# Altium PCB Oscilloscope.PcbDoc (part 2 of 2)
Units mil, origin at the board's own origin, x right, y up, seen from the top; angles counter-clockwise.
Board outline 3937.5 x 3937.5 mil, 4 copper layers (Layer 1, Layer 2, Layer 3, Layer 4), stack 68.734 mil thick; 84 components, 72 nets, 418 pads, 204 vias.
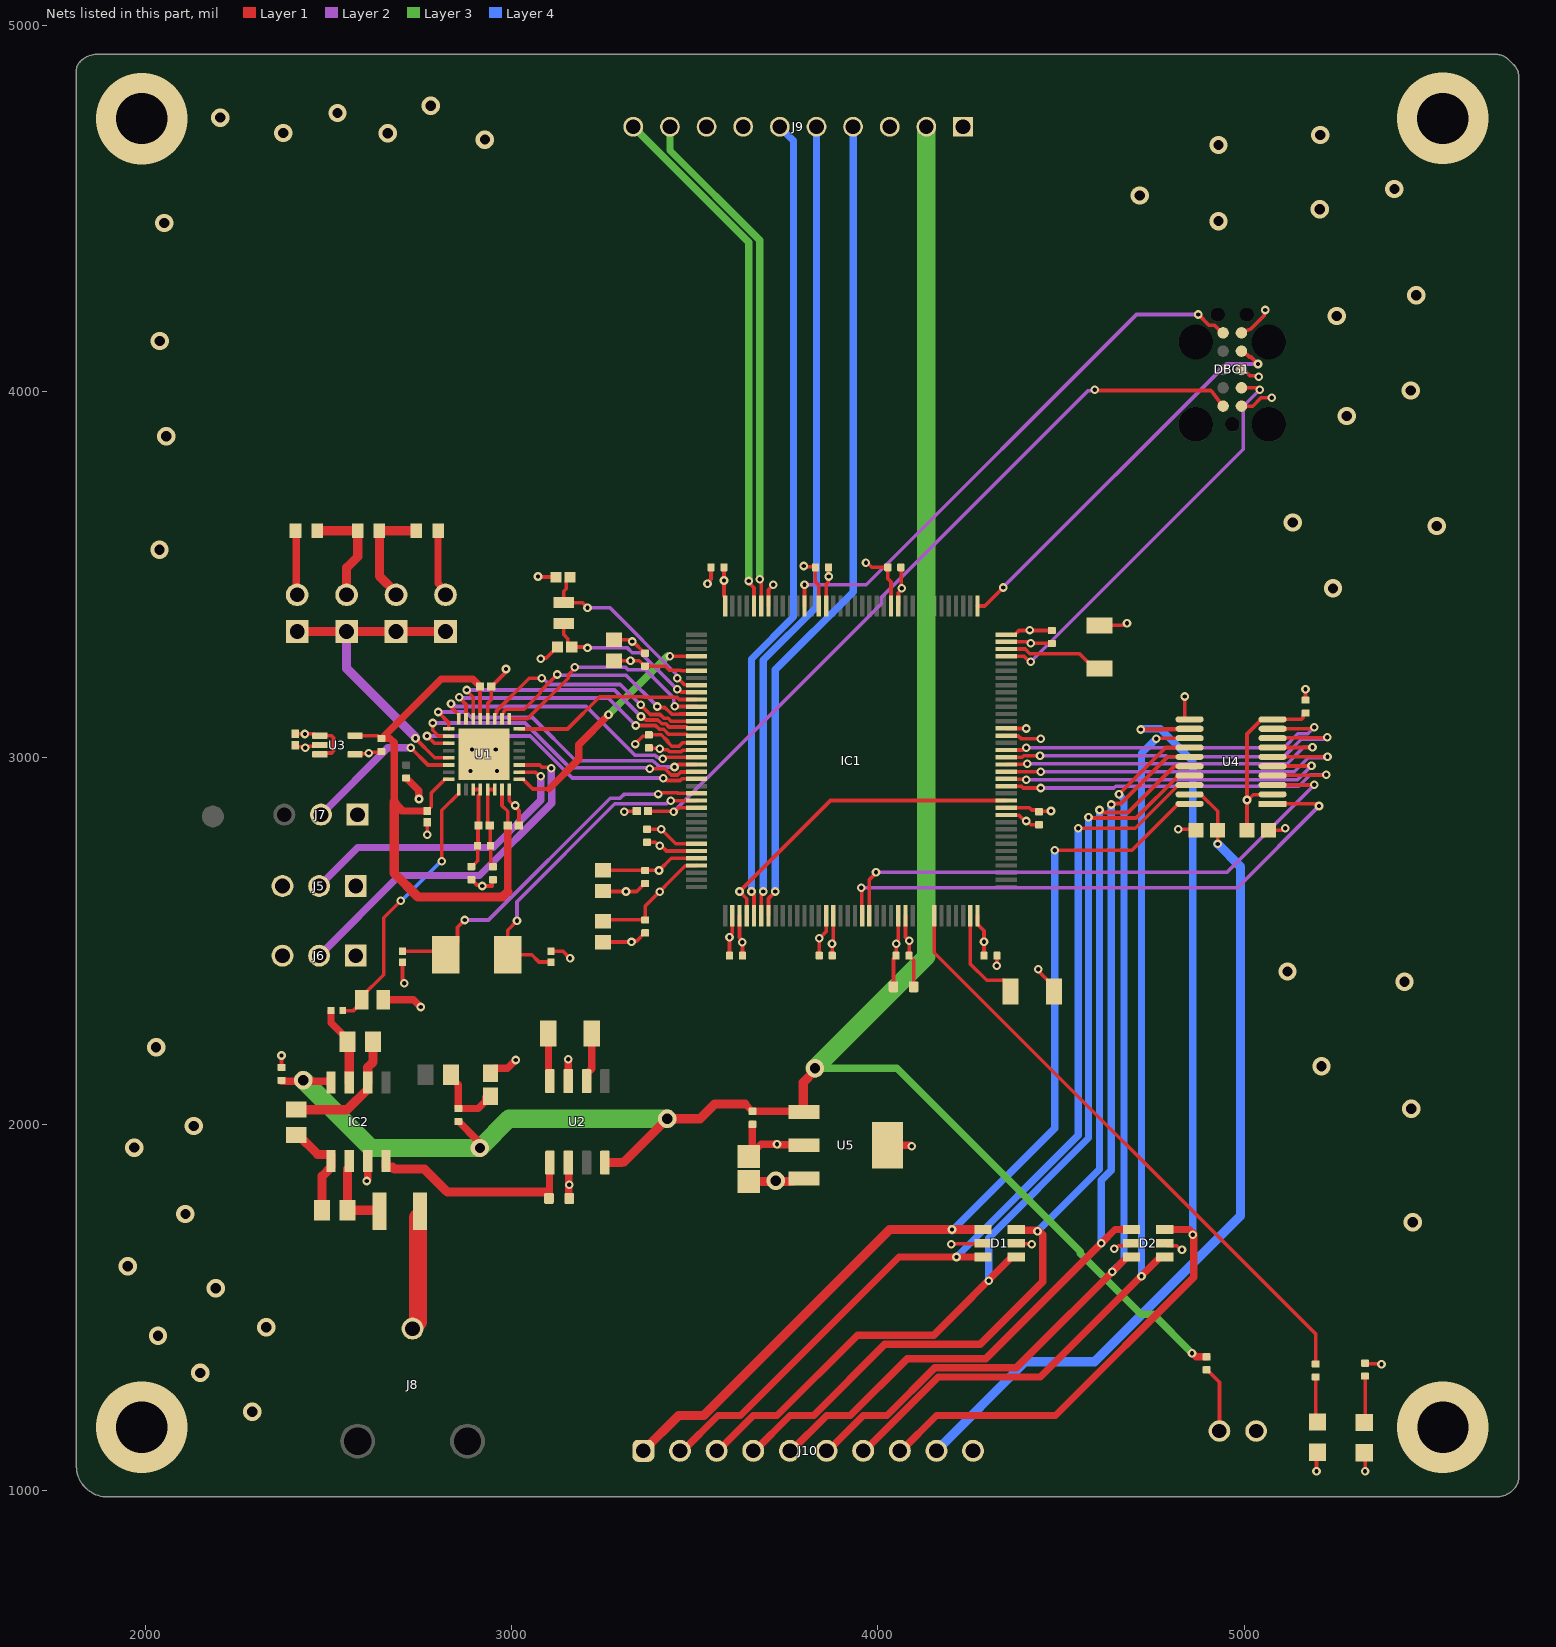
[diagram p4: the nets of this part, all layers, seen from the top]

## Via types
v1: diameter 23.62, hole 11.81, Layer 1 to Layer 4, tented top, 157 vias
v2: diameter 50, hole 28, Layer 1 to Layer 4, 43 vias
v3: diameter 250, hole 140, Layer 1 to Layer 4, 4 vias

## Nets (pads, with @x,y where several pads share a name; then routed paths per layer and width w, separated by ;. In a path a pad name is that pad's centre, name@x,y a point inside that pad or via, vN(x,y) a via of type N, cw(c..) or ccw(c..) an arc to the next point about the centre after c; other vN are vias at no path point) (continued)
3V3: C12.2 C19.2 C20.2 C21.2 C22.2 C23.2 C25.2 C26.2 C27.2 C28.2 C29.2 C30.2 C31.2 C32.2 C33.2 C34.2 C35.2 C36.2 C37.2 C38.2 C40.2 DBG1.1 IC1.6 IC1.17 IC1.30 IC1.32 IC1.33 IC1.39 IC1.52 IC1.62 IC1.72 IC1.84 IC1.95 IC1.108 IC1.121 IC1.131 IC1.144 J1.2 J5.1 J6.1 J7.1 R1.2 R4.2 R13.1 U3.1 U3.3 U4.2 U4.10 U5.3 | length 3599.8
  Layer 1 w10: C12.2@2410,3065.35 2460.2,3065.35 2464.96,3060.59 U3.1@2476.77,3060.59 2508.55,3060.59 2514.41,3054.73 2514.41,3019.13 2508.55,3013.27 2480.63,3013.27 U3.3@2476.77,3009.41 ; C20.2@3250,2553.54 3254.17,2557.72 C19.2@3365,2557.72 3365,2595.7 3474.7,2705.39 3504.09,2705.39 IC1.33@3505,2706.3 ; C38.2@3250,2693.54 3250.83,2692.72 C37.2@3365,2692.72 3402.72,2692.72 3435.98,2725.98 IC1.32@3505,2725.98 ; C22.2@3280,3265 v1(3324.77,3265) 3349.02,3265 3364.02,3250 3420.25,3250 3430.94,3239.31 3461.53,3239.31 3463.05,3237.8 IC1.6@3505,3237.8 ; C35.2@3370,2805 3409.03,2805 3448.67,2765.35 IC1.30@3505,2765.35 ; C36.2@3375,3027.28 3376.14,3026.14 3403.86,3026.14 3407.61,3022.39 3425.8,3022.39 3431.62,3016.57 3463.38,3016.57 3467.16,3020.35 3504.09,3020.35 IC1.17@3505,3021.26 ; C32.2@3580,3520 v1(3580,3484.13) 3580,3440.89 3583.27,3437.62 IC1.144@3583.27,3414.49 ; IC1.39@3622.64,2568.98 3622.64,2509.73 3630.43,2501.94 C27.2@3630.43,2460 ; v1(3797.5,3523.69) 3799.34,3521.84 3827.72,3521.84 C33.2@3829.57,3520 3829.57,3480.7 3839.17,3471.09 IC1.131@3839.17,3414.49 ; C28.2@3875.43,2460 3875.22,2460.22 3875.22,2492.28 v1(3875,2492.5) 3875,2496.19 3878.54,2499.73 IC1.52@3878.54,2568.98 ; v1(3967.5,3532.5) 3971.19,3532.5 3983.69,3520 C34.2@4027.28,3520 4027.39,3519.89 4027.39,3492.61 4027.5,3492.5 4027.5,3488.81 4036.02,3480.29 IC1.121@4036.02,3414.49 ; IC1.62@4075.39,2568.98 4075.39,2510.86 v1(4085.43,2500.82) C26.2@4085.43,2460 4085.43,2459.02 4097.72,2446.73 C25.2@4097.72,2375 ; IC1.72@4272.24,2568.98 4272.24,2545.85 4290,2528.09 v1(4290,2497.73) C29.2@4290,2460 ; IC1.84@4350.51,2863.78 4413.73,2863.78 4419.95,2857.56 4435.16,2857.56 C30.2@4440,2852.72 4441.14,2853.86 4471.36,2853.86 v1(4472.5,2855) ; IC1.95@4350.51,3080.32 4350.67,3080.16 4404.84,3080.16 v1(4405,3080) ; IC1.108@4350.51,3336.22 4373.64,3336.22 4385.14,3347.72 C31.2@4475,3347.72 ; DBG1.1@4992.5,3960 5023.57,3960 5046.07,3982.5 v1(5075,3982.5) ; C23.2@5007.5,2802.5 v1(5007.5,2885) ; U4.2@5077.5,2900.14 5076.24,2898.88 5025.07,2898.88 5011.19,2885 v1(5007.5,2885) ; R4.2@5167.5,3122.07 5166.52,3122.07 5161.67,3117.22 5161.67,3110.72 5155.82,3104.86 5047.02,3104.86 5007.5,3065.34 v1(5007.5,2885) ; R13.1@5330,1347.72 5331.36,1346.36 5373.64,1346.36 v1(5375,1345)
  Layer 1 w20: R1.2@2799.53,3620 2799.53,3476.79 2820,3456.31 J1.2@2820,3445
  Layer 1 w25: C40.2@3647.5,1843.48 3766.24,1843.48 3774.7,1851.95 U5.3@3798.33,1851.95
  other v1: 3630,2496.19 3404.8,2634.8 3402.51,2692.51 3408.82,2804.8 3405,3025 2436.21,3065.15 4415,3348.69
  other v2: 3721.31,1845.34
3V3_ADC: C6.2 C8.2 C9.2 C13.1 U1.7 U1.21 U1.32 U3.5 | length 1746.9
  Layer 1 w10: U3.5@2573.23,3060.59 2636.14,3060.59 2644.02,3052.72 C13.1@2645,3052.72 ; C8.2@2770,2855.79 2780.9,2866.68 2780.9,2904.3 2817.7,2941.1 U1.32@2828.45,2941.1 ; C9.2@2914.29,3195 2914.29,3118.17 2915.16,3117.3 U1.21@2915.16,3106.55 ; U1.7@2974.21,2913.45 2974.21,2869.38 2989.65,2853.95 C6.2@2989.65,2815
  Layer 1 w20: 2700,2855 C8.2@2770,2855 ; 2700,2860 2680,2880 2680,3041 2668.28,3052.72 C13.1@2645,3052.72 2645.67,3052.72 2807.95,3215 2894.29,3215 2912.87,3196.42 2912.87,3195.63 2913.5,3195 C9.2@2914.29,3195 ; 2989.65,2634.65 C6.2@2989.65,2815
  Layer 1 w25: 2680,2880 2680,2685 2745,2620 2975,2620 2989.65,2634.65
5V_BUS: C17.1 C39.2 IC2.8 J9.02 R12.1 R26.1 U2.8 U5.1 | length 6149.2
  Layer 1 w20: C17.1@2372.5,2117.28 2504.7,2117.28 2507.5,2114.49 IC2.8@2507.5,2113.54 ; R26.1@2855,2007.28 2855.67,2007.28 v2@2908.33,1954.62 ; 3637.72,2055 3656.67,2036.04 3656.67,2035.37 3656.83,2035.22 C39.2@3657.5,2035.22 ; C39.2@3657.66,2035.06 U5.1@3796.32,2035.06 ; v1(4857.5,1375) 4858.48,1375 4868.32,1365.16 4897.34,1365.16 R12.1@4897.5,1365
  Layer 1 w25: U2.8@3255,1895.06 3300,1895.06 ; 3307.56,1897.56 v2(3425,2015) 3514.74,2015 3554.74,2055 3637.72,2055 ; U5.1@3796.32,2035.06 3796.32,2113.86 3828.27,2145.81 v2(3828.27,2152.58)
  Layer 3 w20: v2(3828.27,2152.58) 4052.42,2152.58 4552.5,1652.5 4552.5,1646.87 4718.38,1480.99 4751.51,1480.99 v1(4857.5,1375)
  Layer 3 w50: v2(2431.73,2120.22) 2616.73,1935.22 v2(2913.85,1935.22) 2993.64,2015 v2(3425,2015) ; v2(3828.27,2152.58) 3828.19,2152.5 3827.5,2152.5 4132.5,2457.5 J9.02@4132.5,4722.5
-5V: C16.2 IC2.4 U2.5 | length 580.3
  Layer 1 w20: C16.2@3102.44,1797.5 3103.72,1798.78 3103.72,1893.78 U2.5@3105,1895.06
  Layer 1 w25: IC2.4@2657.5,1900 2657.5,1882.78 2657.8,1882.48 2675.02,1882.48 2680,1877.5 2762.5,1877.5 2822.44,1817.56 ; 2825,1815.06 3097.5,1815.06
ADC_CLK: IC1.4 U1.9 | length 667.9
  Layer 1 w10: U1.9@3021.55,2941.1 3032.3,2941.1 3058.4,2915 3102.44,2915 ; v1(3432.5,3277.5) 3432.67,3277.33 3504.83,3277.33 IC1.4@3505,3277.17
  Layer 1 w20: 3102.44,2915 3183.37,2995.94 3183.37,3035.87 v1(3265,3117.5)
  Layer 3 w20: v1(3265,3117.5) 3425,3277.5 v1(3432.5,3277.5)
ANA_IN: J8.1 R5.1 | length 309.3
  Layer 1 w50: J8.1@2730,1442 2730,1444.71 2745.12,1459.82 R5.1@2745.12,1745
ANA_IN_FILT: C48.1 R9.2 U1.1 | length 744.1
  Layer 1 w10: R9.2@2539.17,2310 2568.82,2310 2590.94,2332.13 C48.1@2590.94,2340 2590.94,2347.87 2651.07,2408 2651.07,2563.57 v1(2697.5,2610) ; v1(2810,2717.5) 2810,2856.6 U1.1@2856.01,2902.61
  Layer 4 w10: v1(2697.5,2610) 2700,2610 2807.5,2717.5 v1(2810,2717.5)
ANA_IN_HIGH: IC2.7 R8.2 R9.1 | length 217.2
  Layer 1 w20: R9.1@2507.5,2310 2507.5,2276.46 2553.01,2230.95 R8.2@2553.01,2225
  Layer 1 w25: R8.2@2553.01,2225 2557.2,2220.8 2557.2,2113.84 IC2.7@2557.5,2113.54
D0: IC1.10 U1.16 | length 523.1
  Layer 1 w10: U1.16@3021.55,3078.9 3153.01,3078.9 3240.92,3166.81 3361.53,3166.81 3362.66,3165.69 3451.95,3165.69 3458.59,3159.06 IC1.10@3505,3159.06
D1: IC1.11 U1.17 | length 632.3
  Layer 1 w10: U1.17@2993.9,3106.55 3044.05,3106.55 3155.01,3217.51 3155.01,3226.39 3172.5,3243.88 v1(3172.5,3246.81) ; v1(3445.7,3141.1) 3446.56,3140.23 3504.14,3140.23 IC1.11@3505,3139.37
  Layer 2 w10: v1(3172.5,3246.81) 3312.11,3246.81 3318.92,3240 3366.69,3240 3443.09,3163.59 3443.09,3143.7 v1(3445.7,3141.1)
D2: IC1.12 U1.18 | length 637.7
  Layer 1 w10: U1.18@2974.21,3106.55 2974.21,3117.3 2978.99,3122.08 2978.99,3126.54 2984.85,3132.39 3034.89,3132.39 3078.64,3176.14 3078.64,3181.14 v1(3125,3227.5) ; v1(3398.32,3140.17) 3400.92,3137.56 3418.39,3137.56 3433.23,3122.72 3433.96,3122.72 3437.39,3119.29 3459.27,3119.29 3459.67,3119.69 IC1.12@3505,3119.69
  Layer 2 w10: v1(3125,3227.5) 3127.5,3225 3313.49,3225 v1(3398.32,3140.17)
D3: IC1.13 U1.19 | length 644
  Layer 1 w10: U1.19@2954.62,3117.39 2959.21,3121.98 2959.21,3127.97 3048.74,3217.5 v1(3082.5,3217.5) ; v1(3352.5,3145) 3379.14,3118.36 3405.72,3118.36 3416.36,3107.72 3427.74,3107.72 3435.46,3100 IC1.13@3505,3100
  Layer 2 w10: v1(3082.5,3217.5) 3085.89,3217.5 3103.16,3200.24 3297.26,3200.24 v1(3352.5,3145)
D4: IC1.14 U1.22 | length 756.8
  Layer 1 w10: v1(2877.74,3185.24) 2877.74,3182.79 2895.47,3165.06 U1.22@2895.47,3106.55 ; v1(3353.78,3112.88) 3357.46,3112.88 3366.98,3103.36 3399.5,3103.36 3410.15,3092.72 3421.53,3092.72 3430.15,3084.09 3478.09,3084.09 3481.87,3080.32 IC1.14@3505,3080.32
  Layer 2 w10: v1(2877.74,3185.24) 3281.42,3185.24 v1(3353.78,3112.88)
D5: IC1.15 U1.23 | length 756.8
  Layer 1 w10: v1(2857.5,3165) 2857.5,3163.66 2875.79,3145.37 U1.23@2875.79,3106.55 ; v1(3339.01,3088.36) 3393.29,3088.36 3403.93,3077.72 3415.32,3077.72 3428.62,3064.41 3478.09,3064.41 3481.87,3060.63 IC1.15@3505,3060.63
  Layer 2 w10: v1(2857.5,3165) 2859.07,3163.43 3263.94,3163.43 v1(3339.01,3088.36)
D6: IC1.18 U1.24 | length 783.6
  Layer 1 w10: v1(2834.91,3147.43) 2837.51,3144.82 2837.51,3135.89 2856.1,3117.3 U1.24@2856.1,3106.55 ; v1(3412.53,2997.39) 3416.22,2997.39 3420.41,3001.57 IC1.18@3505,3001.57
  Layer 2 w10: v1(2834.91,3147.43) 2838.59,3147.43 2846.02,3140 3204.15,3140 3336.98,3007.17 3391.98,3007.17 3395.97,3003.19 3397.1,3003.19 3400.29,2999.99 3409.92,2999.99 v1(3412.53,2997.39)
D7: IC1.19 U1.25 | length 827.9
  Layer 1 w10: v1(2800,3125) 2828.45,3096.55 U1.25@2828.45,3078.9 ; v1(3445,2975) 3448.69,2975 3455.58,2981.89 IC1.19@3505,2981.89
  Layer 2 w10: v1(2800,3125) 2875.47,3125 2890.47,3110 3057.5,3110 3175.33,2992.17 3385.77,2992.17 3389.75,2988.19 3390.88,2988.19 3404.07,2975 v1(3445,2975)
D8: IC1.20 U1.26 | length 852.7
  Layer 1 w10: v1(2785,3095) 2785,3075 2800.79,3059.21 U1.26@2828.45,3059.21 ; v1(3377.65,2970.04) 3377.97,2970.36 3418.79,2970.36 3435.97,2953.19 3454.03,2953.19 3462.14,2961.3 3504.09,2961.3 IC1.20@3505,2962.2
  Layer 2 w10: v1(2785,3095) 3037.06,3095 3159.56,2972.5 3375.19,2972.5 v1(3377.65,2970.04)
D9: IC1.21 U1.27 | length 854.7
  Layer 1 w10: v1(2769.58,3059.58) 2789.63,3039.53 U1.27@2828.45,3039.53 ; v1(3414.15,2944.15) 3417.84,2944.15 3423.81,2938.19 3460.25,2938.19 3464.58,2942.52 IC1.21@3505,2942.52
  Layer 2 w10: v1(2769.58,3059.58) 3051.27,3059.58 3165.85,2945 3413.31,2945 v1(3414.15,2944.15)
Debug: IC1.66 R14.1 | length 1654.7
  Layer 1 w10: IC1.66@4154.13,2568.98 4154.13,2468.04 5195,1427.18 R14.1@5195,1345.43
DIN_1: D1.1 J10.1 U4.20 | length 2756.1
  Layer 1 w10: v1(4482.5,2747.5) 4693.83,2747.5 4818.74,2872.4 4848.95,2872.4 U4.20@4851.09,2874.55
  Layer 1 w25: J10.1@3360,1108.51 3456.49,1205 3525,1205 4032.4,1712.4 D1.1@4287.22,1712.4
  Layer 4 w20: v1(4202.39,1712.39) 4202.39,1709.2 4482.5,1989.31 v1(4482.5,2747.5)
DIN_2: D1.3 J10.2 U4.18 | length 2706.8
  Layer 1 w10: v1(4547.5,2807.5) 4702.39,2807.5 4818.6,2923.72 4849.08,2923.72 U4.18@4851.09,2925.73
  Layer 1 w20: J10.2@3460,1108.51 3467.4,1108.51 3563.89,1205 3625,1205 4057.6,1637.6 D1.3@4287.22,1637.6
  Layer 4 w20: v1(4214.89,1637.39) 4547.5,1970 v1(4547.5,2807.5)
DIN_3: D1.4 J10.3 U4.17 | length 2737.1
  Layer 1 w10: v1@4576.81,2835.69 4704.99,2835.69 4820.62,2951.32 U4.17@4851.09,2951.32
  Layer 1 w20: J10.3@3560,1108.51 3563.86,1108.51 3660.36,1205 3725,1205 3944.32,1424.32 4152.68,1424.32 4365.96,1637.6 D1.4@4377.78,1637.6
  Layer 4 w20: v1(4302.39,1572.39) 4302.39,1689.54 4575,1962.14 v1(4575,2837.5)
DIN_4: D1.6 J10.4 U4.16 | length 2705.9
  Layer 1 w10: v1@4605,2850.69 4683.19,2850.69 4808.68,2976.18 4850.36,2976.18 U4.16@4851.09,2976.91
  Layer 1 w20: J10.4@3660,1108.51 3663.86,1108.51 3760.36,1205 3825,1205 4019.32,1399.32 4279.32,1399.32 4450,1570 4450,1698.87 4438.28,1710.59 4379.59,1710.59 D1.6@4377.78,1712.4
  Layer 4 w20: v1(4435.68,1707.98) 4605,1877.31 v1(4605,2857.5)
DIN_5: D2.1 J10.5 U4.15 | length 2659.1
  Layer 1 w10: v1(4637.5,2872.5) 4640.11,2875.11 4663.45,2875.11 4790.85,3002.5 U4.15@4851.09,3002.5
  Layer 1 w20: J10.5@3760,1108.51 3763.86,1108.51 3860.36,1205 3925,1205 4080,1360 4295,1360 v1(4609.89,1674.89) 4647.4,1712.4 D2.1@4692.5,1712.4
  Layer 4 w20: v1(4609.89,1674.89) 4609.89,1846.84 4637.5,1874.45 v1(4637.5,2872.5)
DIN_6: D2.3 J10.6 U4.14 | length 2619.4
  Layer 1 w10: v1(4658.27,2900.77) 4785.59,3028.09 U4.14@4851.09,3028.09
  Layer 1 w20: J10.6@3860,1108.51 3863.86,1108.51 3960.36,1205 4025,1205 4155,1335 4378.09,1335 4680.69,1637.6 D2.3@4692.5,1637.6
  Layer 4 w20: v1(4639.89,1597.39) 4671.81,1629.31 4671.81,2886.26 4658.27,2899.79 v1(4658.27,2900.77)
DIN_7: D2.4 J10.7 U4.13 | length 2618
  Layer 1 w10: v1(4760,3052.5) 4760.59,3053.09 4850.5,3053.09 U4.13@4851.09,3053.68
  Layer 1 w20: J10.7@3960,1108.51 3963.86,1108.51 4165.36,1310 4443.64,1310 4719.21,1585.57 4771.24,1637.6 D2.4@4783.05,1637.6
  Layer 4 w20: v1(4719.89,1584.89) 4719.89,3012.39 v1(4760,3052.5)
DIN_8: D2.6 J10.8 U4.12 | length 2808
  Layer 1 w12: v1(4717.5,3077.5) 4718.4,3078.4 4850.22,3078.4 U4.12@4851.09,3079.27
  Layer 1 w20: J10.8@4060,1108.51 4063.86,1108.51 4160.36,1205 4485,1205 4862.5,1582.5 4862.5,1700.69 4850.78,1712.4 D2.6@4783.05,1712.4
  Layer 4 w20: v1(4717.5,3077.5) 4718.48,3077.5 4720.29,3079.31 4771.11,3079.31 4859.89,2990.52 v1(4859.89,1698.08)
GND: C1.1 C4.2 C5.2 C6.1 C7.1 C8.1 C9.1 C12.1 C13.2 C16.1 C17.2 C19.1 C20.1 C21.1 C22.1 C23.1 C24.1 C25.1 C26.1 C27.1 C28.1 C29.1 C30.1 C31.1 C32.1 C33.1 C34.1 C35.1 C36.1 C37.1 C38.1 C39.1 C40.1 C42.1 C43.1 C44.1 C45.1 C46.2 C47.2 C48.2 D1.2 D1.5 D2.2 D2.5 D3.2 D4.1 D5.1 DBG1.3 DBG1.5 IC1.16 IC1.31 IC1.38 IC1.51 IC1.61 IC1.83 IC1.94 IC1.107 IC1.120 IC1.130 IC1.138 IC2.3 J4.2 J5.3 J6.3 J9.01 J9.03 J9.07 J9.08 J10.10 R3.1 R4.1 R27.2 U1.8 U1.20 U1.33 U2.3 U2.6 U3.2 U3.4 U4.11 U5.2 U5.4 | length 4472.8
  Layer 1 w10: C17.2@2372.5,2155 v1(2372.5,2187.5) ; C12.1@2410,3034.65 2414.54,3030.11 2434.89,3030.11 v1(2437.5,3027.5) 2441.19,3027.5 2444.83,3031.14 2472.91,3031.14 U3.2@2476.77,3035 ; U3.4@2573.23,3009.41 2575,3011.18 2608.27,3011.18 v1(2610.04,3012.95) ; v1@2610.04,3009.41 2615.75,3015.12 2642.84,3015.12 C13.2@2645,3017.28 ; C46.2@2702.5,2442.6 2702.5,2393.69 2707.5,2388.69 v1(2707.5,2385) ; v1(2770,2790) C8.1@2770,2824.29 ; C4.2@2890.35,2667.28 2891.34,2667.28 2906.02,2652.61 2917.39,2652.61 v1(2920,2650) 2947.28,2650 2947.28,2664.57 C5.2@2950,2667.28 ; U1.20@2934.84,3106.55 2934.84,3148.26 2945,3158.41 C9.1@2945,3195 2945.79,3195 2985,3234.21 v1(2985,3242.5) ; U1.8@2993.9,2913.45 2993.9,2882.61 3006.5,2870 v1(3010,2870) 3010,2866.31 3020.35,2855.96 C6.1@3020.35,2815 ; v1(3072.5,3495) 3073.75,3493.75 3120.17,3493.75 C44.1@3121.42,3492.5 ; v1(3080,3270) 3082.61,3272.61 3095.03,3272.61 3124.92,3302.5 C45.1@3125.71,3302.5 ; C47.2@3107.5,2472.4 3140.1,2472.4 v1(3160,2452.5) ; C20.1@3250,2496.46 3251.04,2497.5 v1(3327.5,2497.5) 3330.11,2500.11 3341.84,2500.11 3364.02,2522.28 C19.1@3365,2522.28 ; C38.1@3250,2636.46 3251.46,2635 3341.73,2635 3364.02,2657.28 C37.1@3365,2657.28 ; C22.1@3280,3322.09 3321.73,3322.09 3326.31,3317.5 3331.95,3317.5 3364.02,3285.43 C21.1@3365,3285.43 ; v1(3307.5,2852.5) 3308.75,2853.75 3340.9,2853.75 C1.1@3342.15,2855 ; v1(3337.5,3037.5) 3358.64,3058.64 3369.94,3058.64 3374.02,3062.72 3409.1,3062.72 3425.69,3046.13 3425.69,3043.72 3437.84,3031.57 3457.16,3031.57 3466.53,3040.94 IC1.16@3505,3040.94 ; C35.1@3370,2769.57 3392.85,2769.57 3402.42,2760 3408.69,2760 3423.02,2745.67 IC1.31@3505,2745.67 ; v1(3535,3475) 3535,3478.69 3544.57,3488.25 C32.1@3544.57,3520 ; C27.1@3595,2460 3595,2513.69 3602.95,2521.64 IC1.38@3602.95,2568.98 ; IC1.138@3701.38,3414.49 3701.38,3458.52 3715,3472.15 v1(3715,3472.5) ; C28.1@3840,2460 v1(3840,2507.5) 3841.42,2507.5 3858.86,2524.94 IC1.51@3858.86,2568.98 ; IC1.130@3858.86,3414.49 3858.86,3472.82 3865,3478.97 C33.1@3865,3520 ; C25.1@4042.6,2375 4042.6,2451.61 4050,2459.02 4050,2496.19 4055.71,2501.89 IC1.61@4055.71,2568.98 ; IC1.120@4055.71,3414.49 4056.61,3415.39 4056.61,3450.43 4065,3458.81 v1(4065,3462.5) 4063.86,3463.64 4063.86,3518.86 C34.1@4062.72,3520 ; v1(4200,1672.5) 4201.25,1673.75 4285.97,1673.75 D1.2@4287.22,1675 ; v1(4325,2432.5) 4325.22,2432.72 4325.22,2459.78 C29.1@4325.43,2460 ; IC1.83@4350.51,2844.09 4351.42,2843.19 4385.62,2843.19 4401.31,2827.5 4406.93,2827.5 4417.15,2817.28 C30.1@4440,2817.28 ; IC1.94@4350.51,3060.63 4351.42,3059.72 4383.6,3059.72 4390.83,3052.5 v1(4445,3052.5) ; IC1.107@4350.51,3316.54 4409.78,3316.54 4413.81,3312.5 v1(4417.5,3312.5) 4417.61,3312.39 4474.89,3312.39 C31.1@4475,3312.28 ; D1.5@4377.78,1675 4379.03,1673.75 4418.75,1673.75 v1(4420,1672.5) ; v1(4437.5,2422.5) 4437.5,2419 4480.5,2376 C42.1@4480.5,2362.5 ; C43.1@4605,3361.5 4670.31,3361.5 4676.31,3367.5 v1(4680,3367.5) ; v1(4645,1660) 4648.69,1660 4656.88,1668.19 4685.69,1668.19 D2.2@4692.5,1675 ; D2.5@4783.05,1675 4789.86,1668.19 4815.62,1668.19 4826.52,1657.29 v1(4830.21,1657.29) ; v1(4820,2805) 4865.94,2805 C24.1@4868.44,2802.5 ; v1(4837.5,3167.5) 4837.5,3107.9 4840.53,3104.86 U4.11@4851.09,3104.86 ; DBG1.3@4992.5,4060 4998.32,4060 5015.71,4042.61 5037.39,4042.61 v1(5040,4040) ; DBG1.5@4992.5,4160 5018.35,4170.85 5054.89,4207.39 v1(5057.5,4222.5) ; C23.1@5066.56,2802.5 5103.81,2802.5 5108.81,2807.5 v1(5112.5,2807.5) ; R4.1@5167.5,3157.5 v1(5167.5,3187.5) ; v1(5197.5,1052.5) 5197.5,1101.69 D5.1@5200,1104.19 ; D4.1@5327.5,1103.03 5330,1100.53 v1(5330,1052.5)
  Layer 1 w20: R3.1@2410.47,3620 2412.74,3617.74 2412.74,3447.26 J4.2@2415,3445 ; v1(2605,1845) 2605,1845.98 2607.5,1848.48 IC2.3@2607.5,1900 ; C48.2@2650,2340 2732.5,2340 v1(2752.5,2320) ; C7.1@2713.33,2944.41 2746.78,2910.96 2746.78,2888.22 v1(2747.47,2887.53) ; R27.2@2942.5,2139.04 2942.5,2141.95 2953.33,2152.78 2989.3,2152.78 v1(3011.52,2175) ; U2.6@3155,1895.06 3156.28,1893.78 3156.28,1798.78 C16.1@3157.56,1797.5 ; U2.3@3155,2117.5 v1(3155,2177.5) ; C40.1@3647.5,1911.52 3657.5,1921.52 C39.1@3657.5,1999.78 ; C40.1@3647.5,1911.95 3668.13,1932.58 3668.56,1932.58 3680.98,1945 v1(3725,1945) 3725.69,1944.31 3796.52,1944.31 U5.2@3798.33,1942.5 ; U5.4@4026.67,1942.5 4089.02,1942.5 4091.52,1940 v1(4092.5,1940)
  other v1: 3157.5,1835 4050,2492.5 3595,2510 3312.5,2635 3405,2760 4405,2827.5 2887.98,2964.25 2960.48,2964.25 2892.5,3022.5 2957.5,3022.5 3330,3317.5 3866.06,3494.78
  other v2: 2292.5,1215 2150.41,1321.16 2035,1422.5 2330.72,1445.98 2192.5,1552.5 1952.5,1612.5 5460,1732.5 2110,1755 1970.11,1936.03 2132.5,1995 5455.93,2042.37 5210.91,2157.94 2030,2210 5437.44,2389.1 5118.45,2416.84 5242.5,3462.5 2039.46,3567.99 5525.28,3632.71 5132.5,3642.5 2057.95,3877.74 5280.26,3933.21 5455,4002.5 2040,4137.5 5252.52,4205.98 5470,4262.5 2052.5,4460 4930,4465 5206.29,4497.23 4715,4535 5410,4552.5 4930,4672.5 2927.5,4687.5 5207.5,4700 2376.95,4705.27 2662.5,4705 2205,4747.5 2525,4760 2780,4780
  other v3: 1990.56,1172.5 5542.5,1172.5 1990.56,4744.9 5542.26,4745.27
HSE_IN: C46.1 IC1.23 Y2.1 | length 1015.2
  Layer 1 w10: C46.1@2702.5,2472.4 2810.45,2472.4 Y2.1@2820.35,2462.5 2852.76,2494.9 2852.76,2537.76 v1(2872.5,2557.5) ; v1(3400.52,2901.02) 3404.2,2901.02 3407.49,2904.31 3453.34,2904.31 3454.5,2903.15 IC1.23@3505,2903.15
  Layer 2 w10: v1(2872.5,2557.5) 2937.5,2557.5 3269.31,2889.31 3296.56,2889.31 3308.27,2901.02 v1(3400.52,2901.02)
HSE_OUT: C47.1 IC1.24 Y2.2 | length 885.9
  Layer 1 w10: v1(3015,2555) 2989.65,2529.65 Y2.2@2989.65,2462.5 3055.24,2462.5 3075.15,2442.6 C47.1@3107.5,2442.6 ; v1(3435,2882.5) 3461.81,2882.5 3461.87,2882.56 3504.09,2882.56 IC1.24@3505,2883.46
  Layer 2 w10: v1(3015,2555) 3015,2607.5 3281.81,2874.31 3423.12,2874.31 3431.31,2882.5 v1(3435,2882.5)
I2C1_SCL: IC1.139 J9.09 | length 1411.2
  Layer 1 w10: v1(3677.5,3487.5) 3677.5,3483.81 3681.69,3479.62 IC1.139@3681.69,3414.49
  Layer 3 w20: J9.09@3432.5,4722.5 3432.5,4657.86 3677.5,4412.86 v1(3677.5,3487.5)
I2C1_SDA: IC1.140 J9.10 | length 1444.5
  Layer 1 w10: v1(3647.5,3482.5) 3647.5,3478.81 3662.01,3464.31 IC1.140@3662.01,3414.49
  Layer 3 w20: J9.10@3332.5,4722.5 3647.5,4407.5 v1(3647.5,3482.5)
Log_01: IC1.56 U4.1 | length 1547
  Layer 1 w10: v1(3955,2645) 3956.38,2643.62 3956.38,2569.88 IC1.56@3957.28,2568.98 ; U4.1@5077.5,2874.55 v1@5205.45,2874.55
  Layer 2 w10: v1(3955,2645) 4980.85,2645 5204.15,2868.31 v1(5204.15,2868.7)
Log_02: IC1.57 U4.3 | length 1536.5
  Layer 1 w10: IC1.57@3976.97,2568.98 3976.97,2667.62 3995,2685.65 v1(3995,2687.5) ; U4.3@5077.5,2925.73 5079.27,2925.73 5080,2925 5080.96,2925.96 5191.42,2925.96 v1(5191.65,2926.2)
  Layer 2 w10: v1(3995,2687.5) 4952.96,2687.5 v1(5191.65,2926.2)
Log_03: IC1.87 U4.4 | length 1038.5
  Layer 1 w10: IC1.87@4350.51,2922.83 4391.32,2922.83 4396.65,2917.5 v1(4445,2917.5) ; U4.4@5077.5,2951.32 5078.69,2952.51 5222.96,2952.51 v1(5224.15,2953.7)
  Layer 2 w10: v1(4445,2917.5) 4644.15,2917.5 4649.24,2922.59 5149.09,2922.59 5180.2,2953.7 v1(5224.15,2953.7)
Log_04: IC1.88 U4.5 | length 957
  Layer 1 w10: IC1.88@4350.51,2942.52 4351.42,2941.61 4403.39,2941.61 v1(4405,2940) ; U4.5@5077.5,2976.91 5078.25,2977.66 5182.95,2977.66 v1(5183.7,2978.41)
  Layer 2 w10: v1(4405,2940) 5145.29,2940 v1(5183.7,2978.41)
Log_05: IC1.89 U4.6 | length 1043.7
  Layer 1 w10: IC1.89@4350.51,2962.2 v1(4445,2962.2) ; U4.6@5077.5,3002.5 v1(5227.5,3002.5)
  Layer 2 w10: v1(4445,2962.2) 5136.65,2962.2 5174.67,3000.22 5225.22,3000.22 v1(5227.5,3002.5)
Log_06: IC1.90 U4.7 | length 964.9
  Layer 1 w10: IC1.90@4350.51,2981.89 4351.42,2982.8 4406.28,2982.8 v1(4407.5,2984.02) ; U4.7@5077.5,3028.09 5077.8,3028.39 5186.35,3028.39 v1(5186.65,3028.7)
  Layer 2 w10: v1(4407.5,2984.02) 5117.19,2984.02 5161.88,3028.7 v1(5186.65,3028.7)
Log_07: IC1.91 U4.8 | length 1051.7
  Layer 1 w10: IC1.91@4350.51,3001.57 4394.21,3001.57 4398.47,3005.83 v1(4442.5,3005.83) ; U4.8@5077.5,3053.68 5078.76,3054.94 5225.39,3054.94 v1(5226.65,3056.2)
  Layer 2 w10: v1(4442.5,3005.83) 4787.26,3005.83 4790.59,3002.5 5107.5,3002.5 5155.51,3050.51 5217.28,3050.51 5222.97,3056.2 v1(5226.65,3056.2)
Log_08: IC1.92 U4.9 | length 983
  Layer 1 w10: IC1.92@4350.51,3021.26 4394.94,3021.26 4401.31,3027.64 v1(4405,3027.64) ; U4.9@5077.5,3079.27 5183.54,3079.27 5187.97,3083.7 v1(5191.65,3083.7)
  Layer 2 w10: v1(4405,3027.64) 5108.38,3027.64 5146.25,3065.51 5173.46,3065.51 v1(5191.65,3083.7)
LSE_IN: C44.2 IC1.8 Y1.1 | length 537.3
  Layer 1 w10: C44.2@3160,3492.5 3159.21,3492.5 3149.65,3482.93 3149.65,3461.69 3142.5,3454.55 Y1.1@3142.5,3423.54 3193.96,3423.54 v1(3207.5,3410) ; v1(3452.5,3217.5) 3454.08,3217.5 3472.25,3199.33 3504.09,3199.33 IC1.8@3505,3198.43
  Layer 2 w10: v1(3207.5,3410) 3268.35,3410 3449.89,3228.45 3449.89,3220.11 v1(3452.5,3217.5)
LSE_OUT: C45.2 IC1.9 Y1.2 | length 465.4
  Layer 1 w10: Y1.2@3142.5,3366.46 3142.5,3336.69 3153.94,3325.26 3153.94,3312.07 3163.5,3302.5 C45.2@3164.29,3302.5 3205,3302.5 v1(3207.5,3300) ; v1(3452.5,3187.5) 3456.19,3187.5 3464.04,3179.65 3504.09,3179.65 IC1.9@3505,3178.74
  Layer 2 w10: v1(3207.5,3300) 3316.65,3300 3329.84,3286.81 3352.34,3286.81 3451.65,3187.5 v1(3452.5,3187.5)
MODE: J1.1 J2.1 J3.1 J4.1 U1.29 | length 887.3
  Layer 1 w10: v1(2738.11,3053.72) 2738.11,3052.79 2790.74,3000.16 U1.29@2828.45,3000.16
  Layer 1 w25: J4.1@2415,3345 J3.1@2550,3345 J2.1@2685,3345 J1.1@2820,3345
  Layer 2 w25: J3.1@2550,3345 2550,3243.95 2738.11,3055.84 v1(2738.11,3053.72)
NetC15_1: C15.1 U2.4 | length 131.7
  Layer 1 w20: C15.1@3100.94,2247.5 3100.94,2141.24 3105,2137.18 U2.4@3105,2117.5
NetC15_2: C15.2 U2.2 | length 135.8
  Layer 1 w20: U2.2@3205,2117.5 3205,2137.18 3219.06,2151.24 C15.2@3219.06,2247.5
NetD3_1: D3.1 R12.2 | length 182.1
  Layer 1 w10: R12.2@4897.5,1329.57 4898.48,1329.57 4932.51,1295.54 D3.1@4932.51,1162.51
NetD4_2: D4.2 R13.2 | length 127.6
  Layer 1 w10: D4.2@5327.5,1185.71 5330,1188.21 R13.2@5330,1312.28
NetD5_2: D5.2 R14.2 | length 125.2
  Layer 1 w10: R14.2@5195,1310 5195,1191.87 D5.2@5200,1186.87
NetJ2_2: J2.2 R1.1 R2.2 | length 294.8
  Layer 1 w25: J2.2@2685,3445 2685,3450.79 2639.53,3496.27 R2.2@2639.53,3620 R1.1@2740.47,3620
NetJ3_2: J3.2 R2.1 R3.2 | length 298.6
  Layer 1 w25: R3.2@2469.53,3620 R2.1@2580.47,3620 2580.47,3549.12 2550,3518.65 J3.2@2550,3445
NetR26_2: R26.2 R27.1 R28.1 | length 194.4
  Layer 1 w20: R28.1@2834.49,2135 2834.49,2129.05 2855,2108.54 R26.2@2855,2042.72 2909.26,2042.72 2930,2063.46 R27.1@2930,2073.46
NRST: C1.2 DBG1.10 IC1.25 | length 2151
  Layer 1 w10: C1.2@3369.48,2855 3370.73,2853.75 3441.25,2853.75 v1(3442.5,2852.5) 3446.19,2852.5 3457.47,2863.78 IC1.25@3505,2863.78 ; v1(4592.5,4005) 4595.06,4002.44 4909.08,4002.44 4911.94,3999.57 4912.33,3999.07 DBG1.10@4942.5,3960
  Layer 2 w10: v1(3442.5,2852.5) 4009.58,3419.58 4009.58,3437.92 4574.05,4002.39 4589.89,4002.39 v1(4592.5,4005)
OE: J6.2 U1.11 | length 993.9
  Layer 1 w10: U1.11@3021.55,2980.47 3076.73,2980.47 3083.14,2974.06 3105.94,2974.06 v1(3108.54,2971.46)
  Layer 2 w20: J6.2@2475,2460 2693.97,2678.97 2912.71,2678.97 3110,2876.26 3110,2919.65 3108.54,2921.11 v1(3108.54,2971.46)
R_Feed1: IC2.2 R5.2 R7.2 | length 212.7
  Layer 1 w25: IC2.2@2557.5,1900 2557.5,1882.78 2551.99,1877.27 R7.2@2551.99,1765 R5.2@2627.38,1765
R_Feed2: IC2.6 R6.1 R8.1 | length 353.4
  Layer 1 w25: R6.1@2412.5,2039.49 2551.01,2039.49 2607.2,2095.68 2607.2,2113.25 2607.8,2113.84 2607.8,2155.3 2621.99,2169.49 R8.1@2621.99,2225
REFH: C2.2 C3.2 C4.1 U1.3 U1.4 | length 241.3
  Layer 1 w10: C4.1@2890.35,2702.72 2891.34,2702.72 2907.64,2719.02 C3.2@2907.64,2760 2908.82,2761.18 2908.82,2813.82 C2.2@2910,2815 2910,2897.54 2915.16,2902.7 U1.4@2915.16,2913.45 U1.3@2895.47,2913.45
REFL: C2.1 C3.1 C5.1 U1.5 U1.6 | length 237.4
  Layer 1 w10: C5.1@2950,2702.72 2949.02,2702.72 2944.17,2707.56 2944.17,2708.54 2943.07,2709.65 C3.1@2943.07,2760 2941.89,2761.18 2941.89,2813.82 C2.1@2940.71,2815 2940.47,2815 2934.84,2820.63 U1.5@2934.84,2913.45 U1.6@2954.53,2913.45
SENSE: J7.2 U1.30 | length 443.5
  Layer 1 w10: v1(2725,3027.5) 2772.03,2980.47 U1.30@2828.45,2980.47
  Layer 2 w20: J7.2@2480,2845 2662.5,3027.5 v1(2725,3027.5)
SHDN: J5.2 U1.10 | length 830.7
  Layer 1 w10: U1.10@3021.55,2960.79 3065.53,2960.79 3076.31,2950 v1(3080,2950)
  Layer 2 w20: J5.2@2475,2650 2580,2755 2950.82,2755 3080,2884.18 v1(3080,2950)
SPI_MISO: IC1.42 J9.05 | length 2216
  Layer 1 w10: IC1.42@3681.69,2568.98 3681.69,2625.51 3687.5,2631.31 v1(3687.5,2635)
  Layer 4 w20: v1(3687.5,2635) 3687.5,3266.79 3832.5,3411.79 J9.05@3832.5,4722.5
SPI_MOSI: IC1.43 J9.04 | length 2249.3
  Layer 1 w10: IC1.43@3701.38,2568.98 3701.38,2615.71 3720,2634.33 v1(3720,2635)
  Layer 4 w20: v1(3720,2635) 3720,3240 3932.5,3452.5 J9.04@3932.5,4722.5
SPI_NSS: IC1.40 IC1.85 | length 905.2
  Layer 1 w10: IC1.40@3642.32,2568.98 3642.32,2615.18 v1(3622.5,2635) 3870.96,2883.46 IC1.85@4350.51,2883.46
SPI_SCK: IC1.41 J9.06 | length 2219
  Layer 1 w10: v1(3655,2635) 3655,2631.31 3662.01,2624.31 IC1.41@3662.01,2568.98
  Layer 4 w20: v1(3655,2635) 3655,3269.64 3770,3384.64 3770,4684.36 J9.06@3732.5,4721.86
SWCLK: DBG1.4 IC1.109 | length 1098.9
  Layer 1 w10: IC1.109@4272.24,3414.49 4291.99,3414.49 v1(4342.5,3465) ; DBG1.4@4992.5,4110 4998.32,4110 5014.36,4093.96 5018.54,4093.96 v1(5037.5,4075)
  Layer 2 w10: v1(4342.5,3465) 4342.5,3465.96 4951.54,4075 v1(5037.5,4075)
SWDIO: DBG1.2 IC1.105 | length 1126.5
  Layer 1 w10: IC1.105@4350.51,3277.17 4399.15,3277.17 4413.81,3262.5 v1(4417.5,3262.5) ; DBG1.2@4992.5,4010 5033.81,4010 5038.81,4005 v1(5042.5,4005)
  Layer 2 w10: v1(4417.5,3262.5) 4997.19,3842.19 4997.19,3959.69 v1(5042.5,4005)
SWO: DBG1.6 IC1.133 | length 1526.8
  Layer 1 w10: IC1.133@3799.8,3414.49 3799.9,3414.59 3799.9,3472.4 v1(3800,3472.5) ; v1(4875,4210) 4904.69,4180.31 4919.33,4180.31 4939.65,4160 DBG1.6@4942.5,4160
  Layer 2 w10: v1(3800,3472.5) 3968.75,3472.5 4706.25,4210 v1(4875,4210)
V_Out_Neg: IC2.1 R6.2 R7.1 | length 279.4
  Layer 1 w25: R6.2@2412.5,1970.51 2418.45,1970.51 2471.44,1917.52 2507.2,1917.52 2507.5,1917.22 IC2.1@2507.5,1900 2507.5,1882.78 2483.01,1858.28 R7.1@2483.01,1765
VCAP1: C42.2 IC1.71 | length 280.4
  Layer 1 w10: IC1.71@4252.56,2568.98 4252.56,2437.44 4297,2393 4345.5,2393 4362.5,2376 C42.2@4362.5,2362.5
VCAP2: C43.2 IC1.106 | length 276.6
  Layer 1 w10: IC1.106@4350.51,3296.85 4402.3,3296.85 4414.84,3284.31 4550.69,3284.31 4591.5,3243.5 C43.2@4605,3243.5
VREF: C24.2 J10.9 U4.19 | length 2351.7
  Layer 1 w10: U4.19@4820.62,2900.14 U4.19@4851.09,2900.14 4881.57,2900.14 4927.5,2854.2 v1(4927.5,2765)
  Layer 4 w25: J10.9@4160,1108.51 4402.83,1351.34 4591.34,1351.34 4990,1750 4990,2702.5 v1(4927.5,2765)
pads on no net: DBG1.7 DBG1.8 DBG1.9 DBG1.A DBG1.B DBG1.C DBG1.D DBG1.E DBG1.F DBG1.G IC1.1 IC1.2 IC1.3 IC1.5 IC1.7 IC1.22 IC1.26 IC1.27 IC1.28 IC1.29 IC1.34 IC1.35 IC1.36 IC1.37 IC1.44 IC1.45 IC1.46 IC1.47 IC1.48 IC1.49 IC1.50 IC1.53 IC1.54 IC1.55 IC1.58 IC1.59 IC1.60 IC1.63 IC1.64 IC1.65 IC1.67 IC1.68 IC1.69 IC1.70 IC1.73 IC1.74 IC1.75 IC1.76 IC1.77 IC1.78 IC1.79 IC1.80 IC1.81 IC1.82 IC1.86 IC1.93 IC1.96 IC1.97 IC1.98 IC1.99 IC1.100 IC1.101 IC1.102 IC1.103 IC1.104 IC1.110 IC1.111 IC1.112 IC1.113 IC1.114 IC1.115 IC1.116 IC1.117 IC1.118 IC1.119 IC1.122 IC1.123 IC1.124 IC1.125 IC1.126 IC1.127 IC1.128 IC1.129 IC1.132 IC1.134 IC1.135 IC1.136 IC1.137 IC1.141 IC1.142 IC1.143 J8.2 J8.3 U1.12 U1.13 U1.14 U1.15 U1.28 U2.1 U2.7

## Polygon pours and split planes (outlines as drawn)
3V3 on Layer 2 "3V3_L02_P000" (solid, pour order 0): 1850,4875 1850,1030 5682.5,1030 5687.5,1025 5687.5,4871.72
GND on Layer 3 "GND_L03_P001" (solid, pour order 1): 1850,4875 1850,1030 5682.5,1030 5687.5,1035 5687.5,4871.72
GND on Layer 4 "GND_L04_P002" (solid, pour order 2): 1850,4867.93 1850,1030 5682.5,1030 5687.5,1025 5687.5,4871.72
GND on Layer 1 "GND_L01_P003" (solid, pour order 3): 1850,4867.93 1850,1030 5692.5,1030 5687.5,1035 5687.5,4864.64

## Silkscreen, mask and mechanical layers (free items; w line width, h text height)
Top Overlay:
  drawing of 5 lines, arcs and shapes, not listed
  text "EECS473 Group 14 F25" at 2257.5,4102.49 h60
  text "Oscilloscope & Logic Analyzer Rev2" at 2257.5,3982.49 h60
  text "Mode" at 2497.5,3727.5 h60
  text "3V3" at 2895,3365 h60
  text "GND" at 2182.5,3362.5 h60
  text "Network" at 4695,3257.5 h60
  text "ADC" at 1915,3085 h120
  text "Sense" at 1907.5,2702.5 h60
  text "SHDN" at 1962.5,2602.5 h60
  text "OE" at 2080,2495 h60
  text "5V to 3V3" at 3537.5,1707.5 h60
  text "-5V Gen" at 2927.5,1700 h60
  text "Attenuation" at 2260,1622.5 h60
Mechanical 1:
  circle w10: c5542.26,4745.27 r70.87
  circle w10: c5542.5,1172.5 r70.87
  circle w10: c1990.56,1172.5 r70.87
  circle w10: c1990.56,4744.9 r70.87
  lines w10: 1812.5,1064.32 ccw(c1889.32,1064.32) 1835,1010 1837.75,1007.25 ccw(c1897.5,1067) 1897.5,982.5 5682.5,982.5 5686.72,982.5 ccw(c5686.72,1050.78) 5735,1002.5 ccw(c5698.79,1038.71) 5750,1038.71 5750,1040 5750,4857.5 ccw(c5701.72,4857.5) 5735.86,4891.64 5732.5,4895 5721.64,4905.86 ccw(c5687.5,4871.72) 5687.5,4920 1867.5,4920 1867.25,4920 ccw(c1867.25,4860.25) 1825,4902.5 1821.34,4898.84 ccw(c1842.68,4877.5) 1812.5,4877.5 1812.5,1070 1812.5,1064.32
